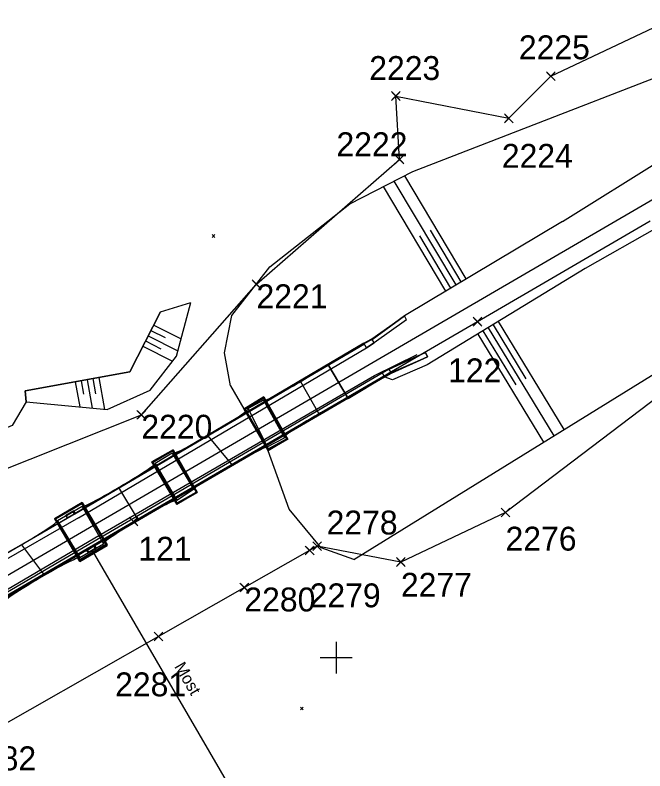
# Model space of a CAD drawing. Extents: x -866402 to -860377, y -1041908 to -1038598.
# Drawn here: x -862740.3 to -862661.2, y -1039814.2 to -1039719.3 of the extents above; entities that cross this region are included whole.
import ezdxf

# ---------------------------------------------------------------- set-up
doc = ezdxf.new("R2010")
doc.units = 0
for name, color, linetype in [('PS 02 trasa', 7, 'Continuous'), ('SZDC', 7, 'Continuous'), ('Vrstva 1', 7, 'Continuous'), ('Vrstva 17', 7, 'Continuous'), ('Vrstva 18', 7, 'Continuous'), ('Vrstva 27', 7, 'Continuous'), ('Vrstva 48', 7, 'Continuous'), ('Vrstva 49', 7, 'Continuous'), ('Vrstva 5', 7, 'Continuous'), ('Vrstva 60', 7, 'Continuous')]:
    doc.layers.add(name, color=color, linetype=linetype)

msp = doc.modelspace()

# ---------------------------------------------------------------- linework, layer by layer
at = {"layer": 'PS 02 trasa'}
msp.add_lwpolyline([(-863126.063, -1039980.929), (-863100.972, -1039979.512), (-863075.698, -1039975.155), (-863051.34, -1039967.955), (-863028.638, -1039958.538), (-863006.197, -1039946.979), (-862984.221, -1039934.346), (-862962.654, -1039921.753), (-862940.81, -1039908.977), (-862919.591, -1039896.575), (-862898.118, -1039884.063), (-862876.452, -1039871.374), (-862855.045, -1039858.711), (-862833.283, -1039846.122), (-862790.121, -1039820.976), (-862768.421, -1039807.915), (-862725.466, -1039782.891), (-862682.227, -1039757.798), (-862660.52, -1039745.143)], dxfattribs=at)
at = {"layer": 'SZDC'}
for points in [[(-863165.8, -1039964.658), (-863118.75, -1039967.2), (-863083.632, -1039964.524), (-863052.89, -1039954), (-863012.743, -1039930.004), (-862976.583, -1039912.971), (-862937.72, -1039894.02), (-862895.01, -1039875.47), (-862835.6, -1039838.65), (-862807.35, -1039814.81), (-862775.54, -1039789.79), (-862724.48, -1039769.5), (-862710.01, -1039753.11), (-862692.04, -1039737.42), (-862692.5, -1039729.46), (-862678.31, -1039732.26), (-862673.01, -1039726.98), (-862636.56, -1039709.7), (-862621.8, -1039702.7), (-862618.74, -1039701.53), (-862617.34, -1039679.93), (-862597.59, -1039662.79), (-862567.2, -1039636.61)], [(-862621.936, -1039738.722), (-862678.709, -1039781.763), (-862691.859, -1039787.99), (-862702.376, -1039785.991), (-862703.328, -1039786.532), (-862711.536, -1039791.199), (-862722.335, -1039797.339), (-862746.625, -1039811.149), (-862749.216, -1039826.631), (-862756.266, -1039834.411), (-862798.224, -1039852.349), (-862808.477, -1039856.796), (-862829.437, -1039865.886), (-862847.784, -1039874.724), (-862872.129, -1039886.289), (-862886.963, -1039890.038), (-862919.94, -1039912.21), (-862947.81, -1039925.24), (-862976.17, -1039939.2), (-863007.49, -1039957.54), (-863029.03, -1039968.68), (-863042.25, -1039972.75), (-863110.71, -1039983.7), (-863135.81, -1039985.12)]]:
    msp.add_lwpolyline(points, dxfattribs=at)
at = {"layer": 'Vrstva 1'}
msp.add_lwpolyline([(-862981.149, -1039929.121), (-862954.673, -1039913.726), (-862917.529, -1039892.093), (-862878.997, -1039869.707), (-862841.948, -1039848.161), (-862805.676, -1039827.062), (-862769.204, -1039805.868), (-862695.361, -1039762.879), (-862669.666, -1039747.949), (-862635.332, -1039727.958)], dxfattribs=at)
at = {"layer": 'Vrstva 17'}
msp.add_line((-862722.095, -1039756.572), (-862725.919, -1039764.118), dxfattribs=at)
for points in [[(-862696.445, -1039760.625), (-862732.862, -1039781.99), (-862733.049, -1039781.698), (-862733.897, -1039782.179), (-862733.747, -1039782.49), (-862770.637, -1039803.933)], [(-862768.22, -1039807.937), (-862731.323, -1039786.458), (-862731.137, -1039786.759), (-862730.291, -1039786.261), (-862730.454, -1039785.968), (-862694.012, -1039764.688)], [(-862725.919, -1039764.118), (-862739.089, -1039766.493), (-862738.963, -1039767.871), (-862740.722, -1039770.864), (-862759.763, -1039778.891)]]:
    msp.add_lwpolyline(points, dxfattribs=at)
at = {"layer": 'Vrstva 18'}
for p, q in [((-862695.46, -1039760.035), (-862691.412, -1039757.059)), ((-862691.142, -1039757.556), (-862691.411, -1039757.059)), ((-862691.141, -1039757.554), (-862691.142, -1039757.556)), ((-862695.502, -1039759.963), (-862695.509, -1039759.968)), ((-862696.518, -1039760.52), (-862732.78, -1039781.879)), ((-862732.396, -1039782.429), (-862696.192, -1039761.091)), ((-862701.025, -1039763.145), (-862696.51, -1039760.593)), ((-862696.511, -1039760.594), (-862696.51, -1039760.593)), ((-862693.353, -1039763.784), (-862688.765, -1039761.683)), ((-862688.779, -1039761.691), (-862693.351, -1039763.782)), ((-862688.518, -1039762.2), (-862688.779, -1039761.691)), ((-862693.1, -1039764.184), (-862688.518, -1039762.2)), ((-862693.058, -1039764.291), (-862688.518, -1039762.2)), ((-862688.522, -1039762.201), (-862693.058, -1039764.29)), ((-862701.025, -1039763.145), (-862698.47, -1039767.448)), ((-862693.93, -1039764.757), (-862730.319, -1039785.946)), ((-862698.47, -1039767.448), (-862693.949, -1039764.717)), ((-862693.949, -1039764.715), (-862693.113, -1039764.191)), ((-862693.932, -1039764.759), (-862693.949, -1039764.715)), ((-862693.949, -1039764.715), (-862693.949, -1039764.717)), ((-862693.058, -1039764.291), (-862693.113, -1039764.191)), ((-862704.472, -1039765.327), (-862702.183, -1039769.382)), ((-862709.148, -1039767.444), (-862711.442, -1039768.815)), ((-862709.147, -1039767.673), (-862711.041, -1039768.725)), ((-862709.126, -1039767.401), (-862709.148, -1039767.444)), ((-862709.148, -1039767.444), (-862706.219, -1039772.524)), ((-862709.147, -1039767.673), (-862706.51, -1039772.373)), ((-862709.08, -1039767.266), (-862706.051, -1039772.554)), ((-862709.074, -1039767.249), (-862706.055, -1039772.571)), ((-862711.621, -1039768.773), (-862708.601, -1039773.97)), ((-862711.442, -1039768.815), (-862711.588, -1039768.764)), ((-862711.588, -1039768.764), (-862708.55, -1039774.027)), ((-862711.041, -1039768.725), (-862708.662, -1039773.538)), ((-862711.615, -1039768.781), (-862708.603, -1039773.972)), ((-862711.442, -1039768.815), (-862708.547, -1039773.795)), ((-862716.139, -1039772.145), (-862713.068, -1039775.819)), ((-862708.662, -1039773.538), (-862706.51, -1039772.373)), ((-862708.547, -1039773.795), (-862706.219, -1039772.524)), ((-862706.219, -1039772.524), (-862706.15, -1039772.589)), ((-862706.15, -1039772.589), (-862708.55, -1039774.027)), ((-862720.542, -1039774.034), (-862722.997, -1039775.472)), ((-862720.608, -1039774.324), (-862722.729, -1039775.6)), ((-862720.608, -1039774.324), (-862717.911, -1039778.836)), ((-862720.558, -1039773.963), (-862720.542, -1039774.034)), ((-862720.542, -1039774.034), (-862717.593, -1039779.205)), ((-862720.5, -1039773.88), (-862717.456, -1039779.228)), ((-862720.499, -1039773.884), (-862717.463, -1039779.22)), ((-862708.55, -1039774.027), (-862708.547, -1039773.795)), ((-862722.997, -1039775.472), (-862723.086, -1039775.397)), ((-862720.022, -1039780.704), (-862723.148, -1039775.428)), ((-862723.146, -1039775.424), (-862720.02, -1039780.707)), ((-862719.972, -1039780.552), (-862722.997, -1039775.472)), ((-862722.729, -1039775.6), (-862720.028, -1039780.224)), ((-862727.355, -1039778.648), (-862724.87, -1039782.725)), ((-862720.028, -1039780.224), (-862717.911, -1039778.836)), ((-862731.946, -1039780.68), (-862735.253, -1039782.626)), ((-862731.923, -1039781.007), (-862735.019, -1039782.798)), ((-862731.934, -1039780.551), (-862731.946, -1039780.68)), ((-862731.946, -1039780.68), (-862728.938, -1039785.784)), ((-862731.923, -1039781.007), (-862729.254, -1039785.697)), ((-862731.913, -1039780.525), (-862728.779, -1039785.829)), ((-862731.913, -1039780.525), (-862728.78, -1039785.83)), ((-862733.82, -1039782.471), (-862732.78, -1039781.879)), ((-862733.801, -1039782.434), (-862732.852, -1039781.9)), ((-862732.986, -1039781.566), (-862732.983, -1039781.555)), ((-862732.852, -1039781.9), (-862732.78, -1039781.879)), ((-862770.621, -1039803.85), (-862733.82, -1039782.471)), ((-862732.396, -1039782.429), (-862770.343, -1039804.324)), ((-862735.403, -1039782.571), (-862732.261, -1039787.876)), ((-862735.402, -1039782.569), (-862732.261, -1039787.879)), ((-862735.253, -1039782.626), (-862735.315, -1039782.556)), ((-862735.253, -1039782.626), (-862732.22, -1039787.718)), ((-862735.019, -1039782.798), (-862732.229, -1039787.431)), ((-862733.982, -1039782.129), (-862733.99, -1039782.142)), ((-862733.801, -1039782.434), (-862733.82, -1039782.471)), ((-862739.557, -1039785.818), (-862736.663, -1039789.674)), ((-862732.229, -1039787.431), (-862729.254, -1039785.697)), ((-862728.938, -1039785.784), (-862732.22, -1039787.718)), ((-862728.771, -1039785.921), (-862728.938, -1039785.784)), ((-862728.78, -1039785.83), (-862728.779, -1039785.829)), ((-862731.364, -1039786.548), (-862768.079, -1039808.066)), ((-862732.207, -1039787.935), (-862728.771, -1039785.921)), ((-862730.319, -1039785.946), (-862731.364, -1039786.548)), ((-862731.353, -1039786.534), (-862730.372, -1039785.93)), ((-862730.67, -1039786.549), (-862700.409, -1039838.493)), ((-862730.319, -1039785.946), (-862730.372, -1039785.93)), ((-862730.372, -1039785.93), (-862730.146, -1039786.242)), ((-862730.146, -1039786.242), (-862730.16, -1039786.233)), ((-862732.22, -1039787.718), (-862732.207, -1039787.935))]:
    msp.add_line(p, q, dxfattribs=at)
for points in [[(-862691.142, -1039757.556), (-862695.2, -1039760.453), (-862695.502, -1039759.963), (-862691.411, -1039757.059)], [(-862691.141, -1039757.554), (-862691.412, -1039757.059), (-862691.411, -1039757.059)], [(-862691.141, -1039757.554), (-862695.204, -1039760.456), (-862695.2, -1039760.453)], [(-862696.518, -1039760.52), (-862696.519, -1039760.521), (-862695.509, -1039759.968)], [(-862695.509, -1039759.968), (-862695.46, -1039760.035), (-862696.511, -1039760.594), (-862696.519, -1039760.521)], [(-862696.192, -1039761.091), (-862696.518, -1039760.52), (-862695.502, -1039759.963)], [(-862695.46, -1039760.035), (-862695.46, -1039760.035), (-862696.51, -1039760.593)], [(-862695.2, -1039760.453), (-862696.192, -1039761.091), (-862696.182, -1039761.084), (-862695.204, -1039760.456)], [(-862688.779, -1039761.691), (-862688.765, -1039761.683), (-862688.522, -1039762.201), (-862688.518, -1039762.2)], [(-862694.218, -1039764.236), (-862694.22, -1039764.238), (-862693.351, -1039763.782), (-862693.353, -1039763.784)], [(-862694.218, -1039764.236), (-862693.93, -1039764.757), (-862693.058, -1039764.29), (-862693.353, -1039763.784), (-862694.218, -1039764.236)], [(-862768.348, -1039807.558), (-862730.588, -1039785.455), (-862694.218, -1039764.236)], [(-862693.949, -1039764.717), (-862693.1, -1039764.184), (-862693.113, -1039764.191)], [(-862693.058, -1039764.29), (-862693.058, -1039764.291), (-862693.932, -1039764.759), (-862693.93, -1039764.757)], [(-862709.074, -1039767.249), (-862711.615, -1039768.781), (-862711.621, -1039768.773), (-862709.08, -1039767.266), (-862709.074, -1039767.249)], [(-862711.588, -1039768.764), (-862709.126, -1039767.401), (-862706.15, -1039772.589)], [(-862708.603, -1039773.972), (-862708.601, -1039773.97), (-862706.051, -1039772.554), (-862706.055, -1039772.571), (-862708.603, -1039773.972)], [(-862720.5, -1039773.88), (-862720.499, -1039773.884), (-862723.148, -1039775.428), (-862723.146, -1039775.424), (-862720.5, -1039773.88)], [(-862723.086, -1039775.397), (-862720.001, -1039780.739), (-862717.463, -1039779.279), (-862720.558, -1039773.963), (-862723.086, -1039775.397)], [(-862720.001, -1039780.739), (-862719.972, -1039780.552), (-862717.593, -1039779.205), (-862717.463, -1039779.279)], [(-862720.022, -1039780.704), (-862720.02, -1039780.707), (-862717.456, -1039779.228), (-862717.463, -1039779.22), (-862720.022, -1039780.704)], [(-862731.913, -1039780.525), (-862731.913, -1039780.525), (-862735.402, -1039782.569), (-862735.403, -1039782.571), (-862731.913, -1039780.525)], [(-862732.207, -1039787.935), (-862735.315, -1039782.556), (-862731.934, -1039780.551), (-862728.771, -1039785.921)], [(-862733.82, -1039782.471), (-862733.99, -1039782.142), (-862732.983, -1039781.555), (-862732.78, -1039781.879)], [(-862732.852, -1039781.9), (-862732.986, -1039781.566), (-862733.982, -1039782.129), (-862733.801, -1039782.434)], [(-862728.78, -1039785.83), (-862732.261, -1039787.876), (-862732.261, -1039787.879), (-862728.779, -1039785.829)], [(-862731.364, -1039786.548), (-862731.154, -1039786.849), (-862730.16, -1039786.233), (-862730.319, -1039785.946)], [(-862731.14, -1039786.852), (-862731.353, -1039786.534), (-862731.364, -1039786.548)], [(-862730.146, -1039786.242), (-862731.14, -1039786.852), (-862731.154, -1039786.849)]]:
    msp.add_lwpolyline(points, dxfattribs=at)
for centre, major_axis, ratio, start_param, end_param in [((-862704.637, -1039765.028), (4.507, 2.661), 0.065296, 3.098751, 5.602555), ((-862701.891, -1039769.728), (4.623, 2.639), 0.083644, 0.691049, 3.157115), ((-862715.826, -1039771.512), (4.782, 2.813), 0.070064, 3.137024, 6.221038), ((-862713.284, -1039776.189), (-4.627, -2.646), 0.040183, 3.171342, 6.28761), ((-862727.326, -1039778.314), (4.597, 2.713), 0.051193, 3.08031, 6.286843), ((-862724.639, -1039782.962), (-4.623, -2.728), 0.05991, 3.187039, 6.314094), ((-862739.739, -1039785.511), (4.717, 2.721), 0.06545, 3.100729, 6.259443), ((-862736.93, -1039790.197), (-4.718, -2.755), 0.05828, 3.198341, 6.299813)]:
    msp.add_ellipse(centre, major_axis=major_axis, ratio=ratio, start_param=start_param, end_param=end_param, dxfattribs=at)
at = {"layer": 'Vrstva 27'}
msp.add_lwpolyline([(-862773.766, -1039810.988), (-862768.443, -1039807.338), (-862730.326, -1039784.966), (-862695.18, -1039764.545), (-862689.81, -1039761.922)], dxfattribs=at)
at = {"layer": 'Vrstva 48'}
for p, q in [((-862684.925, -1039753.19), (-862692.698, -1039740.158)), ((-862683.637, -1039752.422), (-862691.362, -1039739.47)), ((-862686.214, -1039753.959), (-862694.035, -1039740.845)), ((-862684.281, -1039752.806), (-862688.156, -1039746.31)), ((-862685.57, -1039753.574), (-862689.468, -1039747.038)), ((-862722.932, -1039758.223), (-862719.483, -1039759.971)), ((-862680.269, -1039758.187), (-862676.14, -1039764.964)), ((-862679.628, -1039757.797), (-862671.374, -1039771.345)), ((-862723.271, -1039758.892), (-862721.476, -1039759.802)), ((-862681.55, -1039758.968), (-862677.419, -1039765.748)), ((-862680.909, -1039758.577), (-862672.65, -1039772.134)), ((-862723.949, -1039760.23), (-862722.026, -1039761.205)), ((-862723.61, -1039759.561), (-862719.88, -1039761.451)), ((-862682.19, -1039759.358), (-862673.926, -1039772.923)), ((-862724.288, -1039760.899), (-862720.568, -1039762.784)), ((-862730.571, -1039764.957), (-862730.23, -1039766.85)), ((-862729.833, -1039764.824), (-862729.113, -1039768.817)), ((-862732.786, -1039765.356), (-862732.215, -1039768.519)), ((-862732.048, -1039765.223), (-862731.744, -1039766.908)), ((-862731.309, -1039765.09), (-862730.664, -1039768.668))]:
    msp.add_line(p, q, dxfattribs=at)
at = {"layer": 'Vrstva 49'}
for p, q in [((-862671.53, -1039745.201), (-862637.819, -1039724.158)), ((-862715.58, -1039746.861), (-862715.226, -1039747.215)), ((-862715.58, -1039747.215), (-862715.226, -1039746.861)), ((-862697.781, -1039787.665), (-862638.735, -1039751.174)), ((-862738.963, -1039767.871), (-862739.089, -1039766.493)), ((-862705.905, -1039781.345), (-862708.55, -1039774.027)), ((-862704.482, -1039806.221), (-862704.128, -1039806.575)), ((-862704.482, -1039806.575), (-862704.128, -1039806.221))]:
    msp.add_line(p, q, dxfattribs=at)
for points in [[(-862708.316, -1039750.898), (-862698.269, -1039743.022), (-862690.34, -1039738.945), (-862644.047, -1039721.008)], [(-862632.661, -1039730.704), (-862668.702, -1039751.141), (-862688.538, -1039763.225)], [(-862671.53, -1039745.201), (-862691.412, -1039757.059), (-862695.46, -1039760.035), (-862696.51, -1039760.593)], [(-862713.265, -1039765.881), (-862714.047, -1039761.707), (-862713.128, -1039757.022), (-862708.316, -1039750.898)], [(-862739.089, -1039766.493), (-862725.919, -1039764.118), (-862722.095, -1039756.572), (-862718.254, -1039755.402)], [(-862738.963, -1039767.871), (-862728.793, -1039768.848), (-862723.353, -1039766.404), (-862720.062, -1039762.126), (-862718.254, -1039755.402)], [(-862693.949, -1039764.717), (-862698.47, -1039767.448), (-862701.025, -1039763.145), (-862696.51, -1039760.593)], [(-862688.538, -1039763.225), (-862692.905, -1039765.094), (-862693.949, -1039764.717)], [(-862713.265, -1039765.881), (-862711.588, -1039768.764), (-862708.55, -1039774.027)], [(-862697.781, -1039787.665), (-862701.876, -1039786.221), (-862705.905, -1039781.345)]]:
    msp.add_lwpolyline(points, dxfattribs=at)
at = {"layer": 'Vrstva 5'}
for p, q in [((-862700, -1039798), (-862700, -1039802)), ((-862702, -1039800), (-862698, -1039800))]:
    msp.add_line(p, q, dxfattribs=at)
at = {"layer": 'Vrstva 60'}
for p, q in [((-862672.56, -1039727.43), (-862673.56, -1039726.43)), ((-862672.56, -1039726.53), (-862673.56, -1039727.53)), ((-862673.46, -1039727.43), (-862672.46, -1039726.43)), ((-862673.46, -1039726.53), (-862672.46, -1039727.53)), ((-862673.01, -1039726.98), (-862673.01, -1039726.98)), ((-862692.05, -1039729.91), (-862693.05, -1039728.91)), ((-862692.05, -1039729.01), (-862693.05, -1039730.01)), ((-862692.95, -1039729.91), (-862691.95, -1039728.91)), ((-862692.95, -1039729.01), (-862691.95, -1039730.01)), ((-862692.5, -1039729.46), (-862692.5, -1039729.46)), ((-862677.86, -1039732.71), (-862678.86, -1039731.71)), ((-862678.76, -1039732.71), (-862677.76, -1039731.71)), ((-862677.86, -1039731.81), (-862678.86, -1039732.81)), ((-862678.76, -1039731.81), (-862677.76, -1039732.81)), ((-862678.31, -1039732.26), (-862678.31, -1039732.26)), ((-862691.59, -1039737.87), (-862692.59, -1039736.87)), ((-862691.59, -1039736.97), (-862692.59, -1039737.97)), ((-862692.49, -1039737.87), (-862691.49, -1039736.87)), ((-862692.49, -1039736.97), (-862691.49, -1039737.97)), ((-862692.04, -1039737.42), (-862692.04, -1039737.42)), ((-862709.56, -1039753.56), (-862710.56, -1039752.56)), ((-862710.46, -1039753.56), (-862709.46, -1039752.56)), ((-862709.56, -1039752.66), (-862710.56, -1039753.66)), ((-862710.46, -1039752.66), (-862709.46, -1039753.66)), ((-862710.01, -1039753.11), (-862710.01, -1039753.11)), ((-862681.777, -1039758.248), (-862682.777, -1039757.248)), ((-862681.777, -1039757.348), (-862682.777, -1039758.348)), ((-862682.677, -1039758.248), (-862681.677, -1039757.248)), ((-862682.677, -1039757.348), (-862681.677, -1039758.348)), ((-862682.227, -1039757.798), (-862682.227, -1039757.798)), ((-862724.03, -1039769.95), (-862725.03, -1039768.95)), ((-862724.03, -1039769.05), (-862725.03, -1039770.05)), ((-862724.93, -1039769.95), (-862723.93, -1039768.95)), ((-862724.93, -1039769.05), (-862723.93, -1039770.05)), ((-862724.48, -1039769.5), (-862724.48, -1039769.5)), ((-862678.259, -1039782.213), (-862679.259, -1039781.213)), ((-862678.259, -1039781.313), (-862679.259, -1039782.313)), ((-862679.159, -1039782.213), (-862678.159, -1039781.213)), ((-862679.159, -1039781.313), (-862678.159, -1039782.313)), ((-862678.709, -1039781.763), (-862678.709, -1039781.763)), ((-862725.016, -1039783.341), (-862726.016, -1039782.341)), ((-862725.016, -1039782.441), (-862726.016, -1039783.441)), ((-862725.916, -1039783.341), (-862724.916, -1039782.341)), ((-862725.916, -1039782.441), (-862724.916, -1039783.441)), ((-862725.466, -1039782.891), (-862725.466, -1039782.891)), ((-862701.926, -1039786.441), (-862702.926, -1039785.441)), ((-862701.926, -1039785.541), (-862702.926, -1039786.541)), ((-862702.826, -1039786.441), (-862701.826, -1039785.441)), ((-862702.826, -1039785.541), (-862701.826, -1039786.541)), ((-862702.878, -1039786.982), (-862703.878, -1039785.982)), ((-862702.878, -1039786.082), (-862703.878, -1039787.082)), ((-862703.778, -1039786.982), (-862702.778, -1039785.982)), ((-862703.778, -1039786.082), (-862702.778, -1039787.082)), ((-862703.328, -1039786.532), (-862703.328, -1039786.532)), ((-862702.376, -1039785.991), (-862702.376, -1039785.991)), ((-862691.409, -1039788.44), (-862692.409, -1039787.44)), ((-862691.409, -1039787.54), (-862692.409, -1039788.54)), ((-862692.309, -1039788.44), (-862691.309, -1039787.44)), ((-862692.309, -1039787.54), (-862691.309, -1039788.54)), ((-862691.859, -1039787.99), (-862691.859, -1039787.99)), ((-862711.086, -1039791.649), (-862712.086, -1039790.649)), ((-862711.086, -1039790.749), (-862712.086, -1039791.749)), ((-862711.986, -1039791.649), (-862710.986, -1039790.649)), ((-862711.986, -1039790.749), (-862710.986, -1039791.749)), ((-862711.536, -1039791.199), (-862711.536, -1039791.199)), ((-862721.885, -1039797.789), (-862722.885, -1039796.789)), ((-862721.885, -1039796.889), (-862722.885, -1039797.889)), ((-862722.785, -1039797.789), (-862721.785, -1039796.789)), ((-862722.785, -1039796.889), (-862721.785, -1039797.889)), ((-862722.335, -1039797.339), (-862722.335, -1039797.339))]:
    msp.add_line(p, q, dxfattribs=at)

# ---------------------------------------------------------------- texts
at = {"layer": 'Vrstva 18'}
msp.add_text('Most', height=1.5, rotation=300.22364, dxfattribs=at).set_placement((-862720.383, -1039801.109))
at = {"layer": 'Vrstva 60'}
for s, p in [('2225', (-862677.031, -1039724.842)), ('2223', (-862695.841, -1039727.446)), ('2222', (-862699.958, -1039737.015)), ('2224', (-862679.176, -1039738.479)), ('2221', (-862710.01, -1039756.11)), ('122', (-862685.93, -1039765.419)), ('2220', (-862724.48, -1039772.5)), ('2278', (-862701.2, -1039784.534)), ('2276', (-862678.709, -1039786.559)), ('121', (-862724.855, -1039787.826)), ('2277', (-862691.859, -1039792.352)), ('2280', (-862711.536, -1039794.199)), ('2279', (-862703.328, -1039793.68)), ('2281', (-862727.778, -1039804.859)), ('2282', (-862746.625, -1039814.149))]:
    msp.add_text(s, height=3, dxfattribs=at).set_placement(p)

doc.saveas('drawing.dxf')
